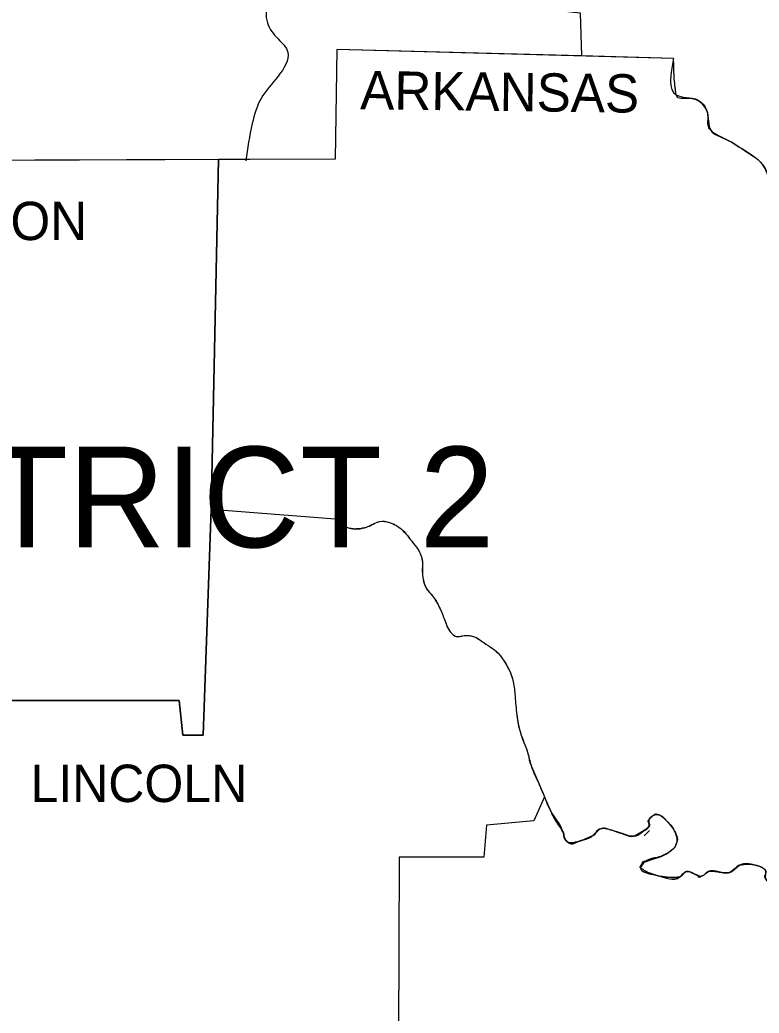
# Model space of a CAD drawing. Extents: x -12863 to 18921, y -8840 to 11152.
# Drawn here: x 14081 to 14893, y 6356 to 7447 of the extents above; entities that cross this region are included whole.
import ezdxf

# ---------------------------------------------------------------- set-up
doc = ezdxf.new("R2010")
doc.units = 0
for name, color, linetype in [('Level 1', 7, 'Continuous'), ('Level 2', 7, 'Continuous'), ('Level 3', 7, 'Continuous'), ('Level 48', 7, 'Continuous')]:
    doc.layers.add(name, color=color, linetype=linetype)

msp = doc.modelspace()

# ---------------------------------------------------------------- linework, layer by layer
at = {"layer": 'Level 1'}
for points in [[(14708.916597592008, 7842.511056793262), (14697.175715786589, 7574.427588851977), (14616.946356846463, 7565.621927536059), (14618.903170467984, 7486.370975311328), (14651.190595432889, 7487.349382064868), (14652.169002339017, 7459.953991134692), (14696.197309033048, 7455.06195713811), (14697.62818181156, 7407.843152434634)], [(14798.930024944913, 7405.163209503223), (14429.092247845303, 7414.947277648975), (14427.135434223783, 7294.603239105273), (13678.654218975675, 7291.668018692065)], [(14299.075112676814, 7294.101041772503), (14291.136886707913, 6910.089359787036), (14427.135434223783, 6899.326884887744)], [(14291.136886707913, 6910.089359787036), (14282.331225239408, 6661.574028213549), (14259.827868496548, 6661.574028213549), (14255.914241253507, 6699.731894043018), (13995.658027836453, 6699.731894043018), (13995.658027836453, 6644.941112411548)], [(14657.061036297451, 6594.063957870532), (14645.320154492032, 6567.646973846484), (14593.464593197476, 6562.754939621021), (14590.529372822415, 6527.532294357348), (14497.580725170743, 6527.532294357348), (14496.602318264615, 6234.988655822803)], [(14766.64259982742, 6551.014057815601), (14769.577820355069, 6553.949278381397), (14772.513040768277, 6556.88449871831), (14772.513040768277, 6556.88449871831)]]:
    msp.add_lwpolyline(points, dxfattribs=at)
for points in [[(14307.769802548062, 7565.621927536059), (14332.22997306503, 7548.98901158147), (14357.66855018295, 7529.420875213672), (14364.517398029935, 7503.003891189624), (14362.560584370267, 7484.414161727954), (14354.733329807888, 7468.759652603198), (14352.776516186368, 7444.299482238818), (14364.517398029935, 7426.688159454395), (14375.279872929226, 7412.0120571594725), (14364.517398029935, 7385.595073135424), (14345.92766837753, 7361.134902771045), (14336.143600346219, 7333.7395118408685), (14329.294752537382, 7292.646425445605)], [(14798.930024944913, 7405.163209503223), (14801.865245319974, 7365.048530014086), (14825.347008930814, 7359.178089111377), (14835.131077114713, 7348.415613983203), (14840.023111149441, 7325.912257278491), (14856.656027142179, 7316.128189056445), (14879.159383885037, 7302.430493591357), (14892.857079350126, 7292.646425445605), (14902.641147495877, 7276.99191632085), (14908.511588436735, 7251.5533390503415), (14924.166097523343, 7234.92042324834), (14945.691047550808, 7227.093168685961), (14961.345556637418, 7208.5034392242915), (14971.129624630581, 7182.086455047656), (14986.784133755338, 7170.345573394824), (15002.438642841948, 7149.799030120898), (15010.265897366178, 7140.9933688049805), (15023.963592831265, 7117.51160519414), (15037.661288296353, 7105.77072338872), (15047.4453565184, 7098.921875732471), (15063.099865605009, 7094.0298415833), (15082.668001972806, 7081.31055302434), (15095.387290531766, 7061.742416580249), (15095.387290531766, 7047.0663142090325), (15090.495256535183, 7024.562957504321), (15086.581629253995, 7001.081193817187), (15084.624815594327, 6974.664209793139), (15082.668001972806, 6951.1824461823), (15091.473663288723, 6931.614309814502), (15086.581629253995, 6902.262105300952), (15076.797561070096, 6886.607596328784), (15075.819154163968, 6865.082646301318), (15072.883933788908, 6832.7952212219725), (15068.970306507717, 6814.205491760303), (15060.164645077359, 6783.874880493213), (15047.4453565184, 6768.220371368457)], [(14427.135434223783, 6899.326884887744), (14441.811536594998, 6889.542816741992), (14462.358079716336, 6890.52122364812), (14476.055775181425, 6896.391664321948), (14486.818250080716, 6895.413257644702), (14501.494352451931, 6886.607596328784), (14511.278420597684, 6874.866714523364), (14518.127268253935, 6866.061053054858), (14523.019302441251, 6852.36335758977), (14523.019302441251, 6839.64406903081), (14527.911336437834, 6822.03274632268), (14533.781777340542, 6815.183898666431), (14541.60903190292, 6802.464609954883), (14546.501066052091, 6790.723728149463), (14549.436286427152, 6782.896473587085), (14560.19876136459, 6770.177185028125), (14569.982829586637, 6771.155591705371), (14578.788491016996, 6770.177185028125), (14590.529372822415, 6763.328337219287), (14608.140695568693, 6749.630641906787), (14611.075915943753, 6745.7170146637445), (14622.816797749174, 6720.278437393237), (14624.773611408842, 6704.623928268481), (14626.730425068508, 6684.077385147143), (14630.64405231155, 6664.509248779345), (14638.47130687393, 6642.984298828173), (14642.384934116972, 6628.308196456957), (14651.190595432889, 6607.7616533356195), (14657.061036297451, 6594.063957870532), (14664.888290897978, 6576.452635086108), (14676.629172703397, 6556.88449871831), (14681.521206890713, 6545.143617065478), (14698.154122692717, 6546.122023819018), (14709.895004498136, 6551.014057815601), (14718.700665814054, 6558.841312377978), (14729.463140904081, 6557.862905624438), (14741.2040227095, 6553.949278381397), (14756.85853179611, 6551.014057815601), (14766.64259982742, 6556.88449871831), (14771.534634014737, 6560.798126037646), (14772.513040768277, 6569.603787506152), (14781.318702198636, 6574.4958215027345), (14791.102770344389, 6567.646973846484), (14801.865245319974, 6551.9924647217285), (14801.865245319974, 6542.208396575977), (14797.951618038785, 6536.337955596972), (14785.232329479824, 6528.5107011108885), (14767.621006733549, 6522.640260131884), (14762.728972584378, 6515.791412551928), (14779.361888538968, 6507.964157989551), (14805.778872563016, 6506.0073443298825), (14812.627720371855, 6511.877785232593), (14830.239042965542, 6506.985751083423), (14837.08789077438, 6511.877785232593), (14860.569654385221, 6510.899378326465), (14871.332129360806, 6518.726632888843), (14892.857079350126, 6517.748226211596), (14899.705927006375, 6512.856191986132), (14899.705927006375, 6504.050530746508), (14917.317249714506, 6500.136903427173), (14930.036538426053, 6503.07212384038), (14946.669454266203, 6498.180089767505), (14961.345556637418, 6490.352835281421), (14969.17281100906, 6479.590360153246), (14978.956879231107, 6467.849478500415), (14987.762540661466, 6470.7846988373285), (14994.611388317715, 6479.590360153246), (15009.287490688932, 6495.244869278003), (15009.287490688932, 6505.0289374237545), (15013.201117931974, 6511.877785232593), (15019.591380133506, 6524.658309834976)]]:
    msp.add_spline(points, degree=3, dxfattribs=at)
at = {"layer": 'Level 48'}
for p, q in [((14291.136886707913, 6910.089359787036), (14299.075112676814, 7294.101041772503)), ((14282.331225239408, 6661.574028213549), (14291.136886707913, 6910.089359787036)), ((13995.658027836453, 6699.731894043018), (14255.914241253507, 6699.731894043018)), ((14791.102770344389, 6567.646973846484), (14788.78337430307, 6569.843044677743)), ((14709.895004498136, 6551.014057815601), (14698.154122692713, 6546.122023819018)), ((14766.64259982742, 6556.88449871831), (14756.858531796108, 6551.0140578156)), ((14767.621006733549, 6522.640260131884), (14774.842735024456, 6525.2607142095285)), ((14774.842735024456, 6525.2607142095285), (14785.232329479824, 6528.5107011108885)), ((14865.950891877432, 6514.854165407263), (14863.380571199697, 6512.475406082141)), ((14870.25435516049, 6518.319516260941), (14868.521212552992, 6517.2123448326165)), ((14871.332129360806, 6518.726632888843), (14870.254355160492, 6518.319516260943)), ((14876.464568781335, 6519.690380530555), (14871.332129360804, 6518.726632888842)), ((14884.909702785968, 6519.662977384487), (14881.936473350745, 6519.890787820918)), ((14892.857079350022, 6517.748226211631), (14884.909702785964, 6519.662977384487)), ((14779.361888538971, 6507.9641579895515), (14775.037509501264, 6509.362388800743)), ((14783.096666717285, 6506.963037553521), (14779.36188853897, 6507.964157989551)), ((14786.010675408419, 6506.371832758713), (14783.096666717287, 6506.963037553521)), ((14805.778872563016, 6506.007344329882), (14799.435028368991, 6505.464116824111)), ((14806.591801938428, 6506.25463626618), (14805.778872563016, 6506.0073443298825)), ((14807.64592161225, 6506.9892162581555), (14806.591801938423, 6506.254636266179)), ((14809.246690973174, 6508.828743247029), (14807.645921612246, 6506.989216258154)), ((14810.825763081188, 6510.725181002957), (14809.246690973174, 6508.828743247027)), ((14811.675772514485, 6511.439318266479), (14810.825763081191, 6510.72518100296)), ((14812.62772037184, 6511.8777852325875), (14811.675772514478, 6511.439318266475)), ((14816.895034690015, 6511.494921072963), (14815.370341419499, 6511.908034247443)), ((14825.970434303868, 6507.333095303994), (14821.432518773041, 6509.408088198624)), ((14830.596385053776, 6507.103115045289), (14830.239042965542, 6506.985751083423)), ((14833.652561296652, 6509.447052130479), (14832.003398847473, 6507.943807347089)), ((14854.895479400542, 6510.404370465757), (14848.800002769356, 6511.25072981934)), ((14860.569654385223, 6510.899378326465), (14854.895479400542, 6510.404370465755)), ((14860.85718239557, 6510.993389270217), (14860.569654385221, 6510.899378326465)), ((14863.3805711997, 6512.475406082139), (14860.857182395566, 6510.9933892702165))]:
    msp.add_line(p, q, dxfattribs=at)
for points in [[(14798.930024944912, 7405.163209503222), (14697.62818181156, 7407.843152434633), (14429.092247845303, 7414.947277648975), (14427.135434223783, 7294.603239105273), (14329.515272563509, 7294.220414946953), (14299.075112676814, 7294.101041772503)], [(14299.075112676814, 7294.101041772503), (13894.844193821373, 7292.5158225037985), (13678.654218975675, 7291.668018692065)], [(14299.075112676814, 7294.101041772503), (14291.136886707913, 6910.089359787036), (14427.135434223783, 6899.326884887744)], [(14255.914241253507, 6699.731894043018), (14259.827868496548, 6661.574028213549), (14282.331225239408, 6661.574028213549)], [(14657.061036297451, 6594.063957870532), (14645.320154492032, 6567.646973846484), (14593.464593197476, 6562.754939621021), (14590.529372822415, 6527.532294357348), (14497.580725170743, 6527.532294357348), (14496.602318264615, 6234.988655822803)]]:
    msp.add_lwpolyline(points, dxfattribs=at)
for points in [[(15026.584089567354, 7114.88705362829), (15023.963592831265, 7117.51160519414), (15019.994945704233, 7123.013884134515), (15016.926980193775, 7129.140353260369), (15013.952897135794, 7135.322889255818), (15010.265897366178, 7140.9933688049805), (15002.438642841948, 7149.799030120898), (14998.43589485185, 7154.855787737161), (14994.579819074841, 7160.053666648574), (14990.739527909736, 7165.260863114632), (14986.784133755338, 7170.345573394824), (14983.179217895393, 7173.587226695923), (14978.939556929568, 7176.196124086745), (14974.70855709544, 7178.814966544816), (14971.129624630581, 7182.086455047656), (14967.836115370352, 7188.164055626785), (14965.905772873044, 7195.006916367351), (14964.141339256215, 7201.993792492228), (14961.345556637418, 7208.5034392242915), (14945.691047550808, 7227.093168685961), (14940.642525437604, 7229.7294498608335), (14935.034444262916, 7231.144447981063), (14929.373427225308, 7232.490620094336), (14924.166097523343, 7234.92042324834), (14919.530587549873, 7238.423466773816), (14915.29861823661, 7242.301376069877), (14908.511588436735, 7251.5533390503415), (14906.353097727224, 7257.764465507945), (14905.373021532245, 7264.272588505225), (14904.494618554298, 7270.780731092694), (14902.641147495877, 7276.99191632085), (14900.713907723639, 7281.231635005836), (14898.595633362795, 7285.385392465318), (14896.054099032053, 7289.256039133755), (14892.857079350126, 7292.646425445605), (14889.542376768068, 7295.344784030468), (14886.161018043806, 7297.844766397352), (14879.159383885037, 7302.430493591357), (14856.656027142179, 7316.128189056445), (14840.023111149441, 7325.912257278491), (14837.072243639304, 7330.218637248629), (14836.647012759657, 7336.212310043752), (14836.686822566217, 7342.681795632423), (14835.131077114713, 7348.415613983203), (14825.347008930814, 7359.178089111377), (14822.609403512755, 7360.539922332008), (14819.26182482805, 7361.08138538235), (14811.843771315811, 7360.985068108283), (14805.306895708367, 7361.4528715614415), (14803.060789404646, 7362.699485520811), (14801.865245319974, 7365.048530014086), (14801.019415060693, 7370.048372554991), (14800.37981969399, 7375.0534525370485), (14799.580536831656, 7385.077131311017), (14798.930024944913, 7405.163209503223)], [(14427.135434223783, 6899.326884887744), (14433.939213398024, 6893.419415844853), (14437.736845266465, 6891.195141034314), (14441.811536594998, 6889.542816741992), (14446.877430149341, 6888.582493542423), (14452.115522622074, 6888.6319425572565), (14462.358079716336, 6890.52122364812), (14465.815553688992, 6891.81741712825), (14469.201469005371, 6893.5745866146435), (14472.5901135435, 6895.2726847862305), (14476.055775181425, 6896.391664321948), (14486.818250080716, 6895.413257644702), (14490.879991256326, 6893.756462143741), (14494.765917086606, 6891.839231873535), (14501.494352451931, 6886.607596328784), (14511.278420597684, 6874.866714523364), (14518.127268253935, 6866.061053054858), (14521.352812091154, 6859.500985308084), (14522.322119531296, 6855.9601700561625), (14523.019302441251, 6852.36335758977), (14523.240005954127, 6849.198836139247), (14523.082868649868, 6846.008732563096), (14522.893948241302, 6842.816119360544), (14523.019302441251, 6839.64406903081), (14524.545523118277, 6830.6414501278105), (14527.911336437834, 6822.03274632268), (14529.262068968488, 6820.163720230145), (14530.81248492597, 6818.520396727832), (14532.37993686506, 6816.92103610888), (14533.781777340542, 6815.183898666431), (14537.964475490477, 6808.985546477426), (14541.60903190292, 6802.464609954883), (14546.501066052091, 6790.723728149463), (14549.436286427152, 6782.896473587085), (14553.53302468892, 6775.370330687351), (14556.483283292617, 6772.310752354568), (14558.23768427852, 6771.106794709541), (14560.19876136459, 6770.177185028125), (14562.643284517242, 6769.83402784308), (14565.09015609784, 6770.2620866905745), (14567.537347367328, 6770.892296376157), (14569.982829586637, 6771.155591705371), (14574.388206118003, 6771.02505251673), (14578.788491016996, 6770.177185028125), (14590.529372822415, 6763.328337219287), (14608.140695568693, 6749.630641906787), (14611.075915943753, 6745.7170146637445), (14614.778926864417, 6739.597550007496), (14618.221865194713, 6733.40238631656), (14622.816797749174, 6720.278437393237), (14624.773611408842, 6704.623928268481), (14626.730425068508, 6684.077385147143), (14626.851023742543, 6683.047457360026)], [(14762.728972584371, 6515.791412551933), (14762.292901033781, 6516.469863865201), (14762.333274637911, 6517.329291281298), (14763.489081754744, 6519.33063915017), (14767.621006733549, 6522.640260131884), (14767.621006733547, 6522.640260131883)], [(14774.842735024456, 6525.2607142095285), (14767.621006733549, 6522.640260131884), (14762.728972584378, 6515.791412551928), (14779.361888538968, 6507.964157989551), (14786.010675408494, 6506.371832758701), (14792.773675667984, 6505.562049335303), (14799.43502836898, 6505.464116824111), (14805.778872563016, 6506.0073443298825), (14807.645921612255, 6506.989216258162), (14809.246690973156, 6508.828743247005), (14810.825763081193, 6510.725181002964), (14812.627720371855, 6511.877785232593), (14814.710747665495, 6512.006587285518), (14816.895034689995, 6511.494921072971), (14821.43251877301, 6509.408088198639), (14825.970434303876, 6507.333095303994), (14830.239042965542, 6506.985751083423), (14832.003398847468, 6507.943807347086), (14833.65256129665, 6509.4470521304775), (14835.307176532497, 6510.942654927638), (14837.08789077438, 6511.877785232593), (14842.718911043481, 6512.166015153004), (14848.800002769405, 6511.250729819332), (14854.895479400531, 6510.404370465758), (14860.569654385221, 6510.899378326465), (14863.380571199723, 6512.475406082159), (14865.950891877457, 6514.854165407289), (14868.521212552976, 6517.212344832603), (14871.332129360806, 6518.726632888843), (14876.464568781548, 6519.690380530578), (14881.936473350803, 6519.8907878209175), (14892.857079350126, 6517.748226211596), (14899.705927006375, 6512.856191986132), (14900.150812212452, 6510.805368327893), (14899.386626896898, 6508.307598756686), (14898.782091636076, 6505.882710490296), (14899.705927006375, 6504.050530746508), (14901.904067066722, 6502.801081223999), (14904.104799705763, 6501.825442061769), (14908.51072915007, 6500.582400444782), (14917.317249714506, 6500.136903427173), (14920.497331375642, 6500.76946893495), (14923.677497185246, 6501.901163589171), (14926.857361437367, 6502.884533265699), (14930.036538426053, 6503.07212384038), (14946.669454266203, 6498.180089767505), (14961.345556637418, 6490.352835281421), (14969.17281100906, 6479.590360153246), (14978.956879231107, 6467.849478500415), (14987.762540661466, 6470.7846988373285), (14994.611388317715, 6479.590360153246), (14998.223655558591, 6483.484696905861), (15002.050206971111, 6487.249460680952), (15005.826374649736, 6491.098301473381), (15009.287490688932, 6495.244869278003), (15009.89980871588, 6497.490044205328), (15009.454257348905, 6500.056321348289), (15008.925322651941, 6502.662889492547), (15009.287490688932, 6505.0289374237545), (15013.201117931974, 6511.877785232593), (15019.27529299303, 6524.1009202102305)], [(14775.037509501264, 6509.362388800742), (14768.165757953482, 6512.158818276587), (14762.728972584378, 6515.791412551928), (14762.728972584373, 6515.791412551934)], [(14868.521212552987, 6517.212344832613), (14868.521212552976, 6517.212344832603), (14865.950891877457, 6514.854165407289), (14865.95089187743, 6514.854165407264)], [(14881.936473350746, 6519.890787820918), (14876.464568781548, 6519.690380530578), (14876.464568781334, 6519.690380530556)], [(14814.710747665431, 6512.0065872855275), (14812.627720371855, 6511.877785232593), (14812.627720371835, 6511.8777852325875)], [(14815.370341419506, 6511.908034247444), (14814.710747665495, 6512.006587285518), (14814.710747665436, 6512.006587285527)], [(14821.432518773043, 6509.408088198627), (14821.43251877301, 6509.408088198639), (14816.895034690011, 6511.494921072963)], [(14830.239042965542, 6506.985751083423), (14825.970434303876, 6507.333095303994), (14825.970434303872, 6507.333095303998)], [(14832.003398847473, 6507.94380734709), (14832.003398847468, 6507.943807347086), (14830.596385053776, 6507.103115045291)], [(14835.307176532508, 6510.942654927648), (14835.307176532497, 6510.942654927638), (14833.65256129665, 6509.4470521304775)], [(14848.800002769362, 6511.250729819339), (14842.718911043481, 6512.166015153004), (14842.718911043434, 6512.1660151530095)]]:
    msp.add_spline(points, degree=3, dxfattribs=at)
for points, degree in [([(14626.851023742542, 6683.047457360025), (14627.613881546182, 6676.784851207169), (14628.905402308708, 6670.600429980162), (14630.64405231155, 6664.509248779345), (14632.748888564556, 6657.135171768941), (14636.193853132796, 6650.2529786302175), (14638.47130687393, 6642.984298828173), (14639.981622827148, 6638.164001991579), (14640.390526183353, 6632.961815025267), (14642.384934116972, 6628.308196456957), (14645.320154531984, 6621.459348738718), (14648.25537500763, 6614.610501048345), (14651.190595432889, 6607.7616533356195), (14653.14740905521, 6603.195754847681), (14655.104222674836, 6598.629856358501), (14657.061036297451, 6594.063957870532), (14659.591623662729, 6588.1592539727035), (14662.21934815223, 6582.295866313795), (14664.888290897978, 6576.452635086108), (14668.04855110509, 6569.533741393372), (14672.863815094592, 6563.434275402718), (14676.629172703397, 6556.88449871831), (14678.72787156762, 6553.2338470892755), (14678.242770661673, 6548.3598870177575), (14681.521206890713, 6545.143617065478), (14685.815803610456, 6540.930455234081), (14692.934508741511, 6544.387275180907), (14698.154122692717, 6546.122023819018), (14702.138704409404, 6547.446307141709), (14706.154406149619, 6549.025742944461), (14709.895004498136, 6551.014057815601), (14713.359832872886, 6552.85578717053), (14714.996304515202, 6557.873078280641), (14718.700665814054, 6558.841312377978), (14722.098555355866, 6559.729441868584), (14726.025143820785, 6558.881093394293), (14729.463140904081, 6557.862905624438), (14733.400323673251, 6556.69688039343), (14737.251815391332, 6555.1209429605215), (14741.2040227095, 6553.949278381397), (14746.290330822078, 6552.441400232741), (14751.845734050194, 6549.970961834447), (14756.85853179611, 6551.014057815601), (14760.449625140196, 6551.761316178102), (14763.427157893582, 6554.653446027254), (14766.64259982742, 6556.88449871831), (14768.408081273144, 6558.109488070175), (14770.0316155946, 6559.356204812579), (14771.534634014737, 6560.798126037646), (14773.660223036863, 6562.837310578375), (14770.102195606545, 6567.056543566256), (14772.513040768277, 6569.603787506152), (14775.25408043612, 6572.499907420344), (14778.522056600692, 6575.24702865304), (14781.318702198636, 6574.4958215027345), (14784.634420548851, 6573.6051861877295), (14787.930327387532, 6570.785357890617), (14791.102770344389, 6567.646973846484), (14796.14905059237, 6562.654869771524), (14799.400575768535, 6557.877745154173), (14801.865245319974, 6551.9924647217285), (14803.134614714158, 6548.961391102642), (14803.052168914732, 6545.270583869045), (14801.865245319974, 6542.208396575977), (14801.009342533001, 6540.000221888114), (14799.850574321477, 6537.971112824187), (14797.951618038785, 6536.337955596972), (14793.931940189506, 6532.880916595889), (14789.687977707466, 6530.724138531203), (14785.232329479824, 6528.5107011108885), (14781.952957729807, 6526.881603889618), (14778.391899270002, 6526.186184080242), (14774.842735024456, 6525.260714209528)], 3), ([(14657.823901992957, 6592.29184233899), (14657.568677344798, 6592.882147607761), (14657.314370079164, 6593.4728457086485), (14657.061036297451, 6594.063957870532)], 2), ([(14681.521206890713, 6545.143617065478), (14678.242770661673, 6548.3598870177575), (14678.72787156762, 6553.2338470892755), (14676.629172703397, 6556.88449871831), (14672.863815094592, 6563.434275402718), (14668.04855110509, 6569.533741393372), (14664.888290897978, 6576.452635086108), (14662.486532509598, 6581.710908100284), (14660.118152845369, 6586.985503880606), (14657.823901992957, 6592.29184233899)], 3), ([(14772.513040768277, 6569.603787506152), (14770.102195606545, 6567.056543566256), (14773.660223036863, 6562.837310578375), (14771.534634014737, 6560.798126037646), (14770.171595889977, 6559.49049495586), (14768.709444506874, 6558.34340162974), (14767.132196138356, 6557.227464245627)], 3), ([(14788.78337430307, 6569.843044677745), (14786.33669031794, 6572.035218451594), (14783.833393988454, 6573.820349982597), (14781.318702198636, 6574.4958215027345), (14778.522056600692, 6575.24702865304), (14775.25408043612, 6572.499907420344), (14772.513040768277, 6569.603787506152)], 3), ([(14729.463140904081, 6557.862905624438), (14726.025143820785, 6558.881093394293), (14722.098555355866, 6559.729441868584), (14718.700665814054, 6558.841312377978), (14716.507890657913, 6558.268171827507), (14715.03969974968, 6556.276250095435), (14713.487949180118, 6554.364048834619)], 3), ([(14801.865245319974, 6551.9924647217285), (14799.400575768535, 6557.877745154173), (14796.14905059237, 6562.654869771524), (14791.102770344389, 6567.646973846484)], 2), ([(14713.487949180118, 6554.364048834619), (14712.41825233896, 6553.045875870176), (14711.308847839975, 6551.765586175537), (14709.895004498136, 6551.014057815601)], 2), ([(14756.85853179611, 6551.014057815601), (14751.845734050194, 6549.970961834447), (14746.290330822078, 6552.441400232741), (14741.2040227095, 6553.949278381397), (14737.251815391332, 6555.1209429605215), (14733.400323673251, 6556.69688039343), (14729.463140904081, 6557.862905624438)], 3), ([(14767.132196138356, 6557.227464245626), (14766.970217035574, 6557.112860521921), (14766.807024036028, 6556.998585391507), (14766.64259982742, 6556.88449871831)], 2), ([(14797.951618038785, 6536.337955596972), (14799.850574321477, 6537.971112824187), (14801.009342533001, 6540.000221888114), (14801.865245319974, 6542.208396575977), (14803.052168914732, 6545.270583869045), (14803.134614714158, 6548.961391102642), (14801.865245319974, 6551.9924647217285)], 3), ([(14698.154122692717, 6546.122023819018), (14692.934508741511, 6544.387275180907), (14685.815803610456, 6540.930455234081), (14681.521206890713, 6545.143617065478)], 2), ([(14785.232329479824, 6528.5107011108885), (14789.687977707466, 6530.724138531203), (14793.931940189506, 6532.880916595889), (14797.951618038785, 6536.337955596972)], 2), ([(14799.435028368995, 6505.464116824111), (14795.07597818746, 6505.307830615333), (14790.505255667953, 6505.578984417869), (14786.010675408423, 6506.371832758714)], 2), ([(14842.718911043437, 6512.166015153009), (14840.742687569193, 6512.341215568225), (14838.841476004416, 6512.315830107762), (14837.08789077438, 6511.877785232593), (14836.459897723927, 6511.7209128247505), (14835.873028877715, 6511.378489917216), (14835.30717653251, 6510.942654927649)], 3)]:
    msp.add_open_spline(points, degree=degree, dxfattribs=at)

# ---------------------------------------------------------------- texts
at = {"layer": 'Level 2'}
msp.add_text('ARKANSAS', height=42.061709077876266, rotation=359.2678250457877, dxfattribs=at).set_placement((14454.530825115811, 7349.394020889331))
for s, height, p in [('JEFFERSON', 42.07344995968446, (13820.523207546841, 7205.568218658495)), ('LINCOLN', 41.09308632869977, (14092.520302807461, 6588.193516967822))]:
    msp.add_text(s, height=height, dxfattribs=at).set_placement(p)
at = {"layer": 'Level 3'}
msp.add_text('DISTRICT 2', height=110.55801354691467, dxfattribs=at).set_placement((13797.041443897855, 6868.0178667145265))

doc.saveas('drawing.dxf')
